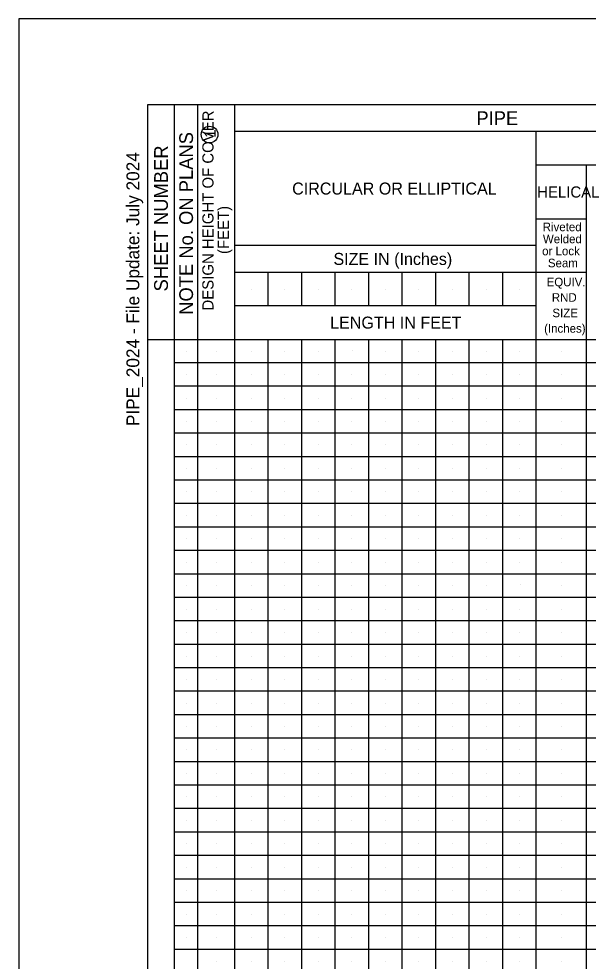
# Model space of a CAD drawing. Extents: x 0 to 1.42, y 0 to 0.92.
# Drawn here: x 0 to 0.2763, y 0.4596 to 0.9167 of the extents above; entities that cross this region are included whole.
import ezdxf

# ---------------------------------------------------------------- set-up
doc = ezdxf.new("R2010")
doc.units = 0
for name, color, linetype in [('#plot_shape', 7, 'Continuous'), ('P_ODOT_PLAN_Border', 7, 'Continuous'), ('P_ODOT_PLAN_General', 7, 'Continuous'), ('P_RDWY_PLAN_NotesTx', 7, 'Continuous')]:
    doc.layers.add(name, color=color, linetype=linetype)

msp = doc.modelspace()

# ---------------------------------------------------------------- linework, layer by layer
at = {"layer": '#plot_shape'}
msp.add_lwpolyline([(0, 0), (1.41667, 0), (1.41667, 0.91667), (0, 0.91667)], close=True, dxfattribs=at)
at = {"layer": 'P_ODOT_PLAN_Border'}
msp.add_lwpolyline([(0.0625, 0.04167), (1.39583, 0.04167), (1.39583, 0.875), (0.0625, 0.875)], close=True, dxfattribs=at)
at = {"layer": 'P_ODOT_PLAN_General'}
for p, q in [((0.07551, 0.26037), (0.07551, 0.875)), ((0.08689, 0.26037), (0.08689, 0.875)), ((0.10478, 0.26037), (0.10478, 0.875)), ((0.35681, 0.86199), (0.10478, 0.86199)), ((0.25112, 0.26037), (0.25112, 0.86199)), ((0.35681, 0.84573), (0.25112, 0.84573)), ((0.27551, 0.26037), (0.27551, 0.84573)), ((0.25112, 0.81972), (0.27551, 0.81972)), ((0.25112, 0.80671), (0.10478, 0.80671)), ((0.27551, 0.7937), (0.10478, 0.7937)), ((0.12104, 0.77744), (0.12104, 0.7937)), ((0.1373, 0.77744), (0.1373, 0.7937)), ((0.15356, 0.77744), (0.15356, 0.7937)), ((0.16982, 0.77744), (0.16982, 0.7937)), ((0.18608, 0.77744), (0.18608, 0.7937)), ((0.20234, 0.77744), (0.20234, 0.7937)), ((0.2186, 0.77744), (0.2186, 0.7937)), ((0.23486, 0.77744), (0.23486, 0.7937)), ((0.11291, 0.78557), (0.11291, 0.78557)), ((0.12917, 0.78557), (0.12917, 0.78557)), ((0.14543, 0.78557), (0.14543, 0.78557)), ((0.16169, 0.78557), (0.16169, 0.78557)), ((0.17795, 0.78557), (0.17795, 0.78557)), ((0.19421, 0.78557), (0.19421, 0.78557)), ((0.21047, 0.78557), (0.21047, 0.78557)), ((0.22673, 0.78557), (0.22673, 0.78557)), ((0.24299, 0.78557), (0.24299, 0.78557)), ((0.25112, 0.77744), (0.10478, 0.77744)), ((0.0625, 0.76118), (0.35681, 0.76118)), ((0.12104, 0.26037), (0.12104, 0.76118)), ((0.1373, 0.26037), (0.1373, 0.76118)), ((0.15356, 0.26037), (0.15356, 0.76118)), ((0.16982, 0.26037), (0.16982, 0.76118)), ((0.18608, 0.26037), (0.18608, 0.76118)), ((0.20234, 0.26037), (0.20234, 0.76118)), ((0.2186, 0.26037), (0.2186, 0.76118)), ((0.23486, 0.26037), (0.23486, 0.76118)), ((0.0812, 0.75549), (0.0812, 0.75549)), ((0.09583, 0.75549), (0.09583, 0.75549)), ((0.11291, 0.75549), (0.11291, 0.75549)), ((0.12917, 0.75549), (0.12917, 0.75549)), ((0.14543, 0.75549), (0.14543, 0.75549)), ((0.16176, 0.75562), (0.16176, 0.75562)), ((0.17795, 0.75549), (0.17795, 0.75549)), ((0.19421, 0.75549), (0.19421, 0.75549)), ((0.21047, 0.75549), (0.21047, 0.75549)), ((0.22673, 0.75549), (0.22673, 0.75549)), ((0.24299, 0.75549), (0.24299, 0.75549)), ((0.26331, 0.75549), (0.26331, 0.75549)), ((0.25112, 0.7498), (0.07551, 0.7498)), ((0.50965, 0.7498), (0.25112, 0.7498)), ((0.0812, 0.74411), (0.0812, 0.74411)), ((0.09583, 0.74411), (0.09583, 0.74411)), ((0.11291, 0.74411), (0.11291, 0.74411)), ((0.12917, 0.74411), (0.12917, 0.74411)), ((0.14543, 0.74411), (0.14543, 0.74411)), ((0.16169, 0.74411), (0.16169, 0.74411)), ((0.17795, 0.74411), (0.17795, 0.74411)), ((0.19421, 0.74411), (0.19421, 0.74411)), ((0.21047, 0.74411), (0.21047, 0.74411)), ((0.22673, 0.74411), (0.22673, 0.74411)), ((0.24299, 0.74411), (0.24299, 0.74411)), ((0.26331, 0.74411), (0.26331, 0.74411)), ((0.25112, 0.73842), (0.07551, 0.73842)), ((0.50965, 0.73842), (0.25112, 0.73842)), ((0.0812, 0.73273), (0.0812, 0.73273)), ((0.09583, 0.73273), (0.09583, 0.73273)), ((0.11291, 0.73273), (0.11291, 0.73273)), ((0.12917, 0.73273), (0.12917, 0.73273)), ((0.14543, 0.73273), (0.14543, 0.73273)), ((0.16169, 0.73273), (0.16169, 0.73273)), ((0.17795, 0.73273), (0.17795, 0.73273)), ((0.19421, 0.73273), (0.19421, 0.73273)), ((0.21047, 0.73273), (0.21047, 0.73273)), ((0.22673, 0.73273), (0.22673, 0.73273)), ((0.24299, 0.73273), (0.24299, 0.73273)), ((0.26331, 0.73273), (0.26331, 0.73273)), ((0.25112, 0.72703), (0.07551, 0.72703)), ((0.50965, 0.72703), (0.25112, 0.72703)), ((0.0812, 0.72134), (0.0812, 0.72134)), ((0.09583, 0.72134), (0.09583, 0.72134)), ((0.11291, 0.72134), (0.11291, 0.72134)), ((0.12917, 0.72134), (0.12917, 0.72134)), ((0.14543, 0.72134), (0.14543, 0.72134)), ((0.16169, 0.72134), (0.16169, 0.72134)), ((0.17795, 0.72134), (0.17795, 0.72134)), ((0.19421, 0.72134), (0.19421, 0.72134)), ((0.21047, 0.72134), (0.21047, 0.72134)), ((0.22673, 0.72134), (0.22673, 0.72134)), ((0.24299, 0.72134), (0.24299, 0.72134)), ((0.26331, 0.72134), (0.26331, 0.72134)), ((0.25112, 0.71565), (0.07551, 0.71565)), ((0.50965, 0.71565), (0.25112, 0.71565)), ((0.0812, 0.70996), (0.0812, 0.70996)), ((0.09583, 0.70996), (0.09583, 0.70996)), ((0.11291, 0.70996), (0.11291, 0.70996)), ((0.12917, 0.70996), (0.12917, 0.70996)), ((0.14543, 0.70996), (0.14543, 0.70996)), ((0.16169, 0.70996), (0.16169, 0.70996)), ((0.17795, 0.70996), (0.17795, 0.70996)), ((0.19421, 0.70996), (0.19421, 0.70996)), ((0.21047, 0.70996), (0.21047, 0.70996)), ((0.22673, 0.70996), (0.22673, 0.70996)), ((0.24299, 0.70996), (0.24299, 0.70996)), ((0.26331, 0.70996), (0.26331, 0.70996)), ((0.25112, 0.70427), (0.07551, 0.70427)), ((0.50965, 0.70427), (0.25112, 0.70427)), ((0.0812, 0.69858), (0.0812, 0.69858)), ((0.09583, 0.69858), (0.09583, 0.69858)), ((0.11291, 0.69858), (0.11291, 0.69858)), ((0.12917, 0.69858), (0.12917, 0.69858)), ((0.14543, 0.69858), (0.14543, 0.69858)), ((0.16169, 0.69858), (0.16169, 0.69858)), ((0.17795, 0.69858), (0.17795, 0.69858)), ((0.19421, 0.69858), (0.19421, 0.69858)), ((0.21047, 0.69858), (0.21047, 0.69858)), ((0.22673, 0.69858), (0.22673, 0.69858)), ((0.24299, 0.69858), (0.24299, 0.69858)), ((0.26331, 0.69858), (0.26331, 0.69858)), ((0.25112, 0.69289), (0.07551, 0.69289)), ((0.50965, 0.69289), (0.25112, 0.69289)), ((0.0812, 0.6872), (0.0812, 0.6872)), ((0.09583, 0.6872), (0.09583, 0.6872)), ((0.11291, 0.6872), (0.11291, 0.6872)), ((0.12917, 0.6872), (0.12917, 0.6872)), ((0.14543, 0.6872), (0.14543, 0.6872)), ((0.16169, 0.6872), (0.16169, 0.6872)), ((0.17795, 0.6872), (0.17795, 0.6872)), ((0.19421, 0.6872), (0.19421, 0.6872)), ((0.21047, 0.6872), (0.21047, 0.6872)), ((0.22673, 0.6872), (0.22673, 0.6872)), ((0.24299, 0.6872), (0.24299, 0.6872)), ((0.26331, 0.6872), (0.26331, 0.6872)), ((0.25112, 0.68151), (0.07551, 0.68151)), ((0.50965, 0.68151), (0.25112, 0.68151)), ((0.0812, 0.67582), (0.0812, 0.67582)), ((0.09583, 0.67582), (0.09583, 0.67582)), ((0.11291, 0.67582), (0.11291, 0.67582)), ((0.12917, 0.67582), (0.12917, 0.67582)), ((0.14543, 0.67582), (0.14543, 0.67582)), ((0.16169, 0.67582), (0.16169, 0.67582)), ((0.17795, 0.67582), (0.17795, 0.67582)), ((0.19421, 0.67582), (0.19421, 0.67582)), ((0.21047, 0.67582), (0.21047, 0.67582)), ((0.22673, 0.67582), (0.22673, 0.67582)), ((0.24299, 0.67582), (0.24299, 0.67582)), ((0.26331, 0.67582), (0.26331, 0.67582)), ((0.25112, 0.67012), (0.07551, 0.67012)), ((0.50965, 0.67012), (0.25112, 0.67012)), ((0.0812, 0.66443), (0.0812, 0.66443)), ((0.09583, 0.66443), (0.09583, 0.66443)), ((0.11291, 0.66443), (0.11291, 0.66443)), ((0.12917, 0.66443), (0.12917, 0.66443)), ((0.14543, 0.66443), (0.14543, 0.66443)), ((0.16169, 0.66443), (0.16169, 0.66443)), ((0.17795, 0.66443), (0.17795, 0.66443)), ((0.19421, 0.66443), (0.19421, 0.66443)), ((0.21047, 0.66443), (0.21047, 0.66443)), ((0.22673, 0.66443), (0.22673, 0.66443)), ((0.24299, 0.66443), (0.24299, 0.66443)), ((0.26331, 0.66443), (0.26331, 0.66443)), ((0.25112, 0.65874), (0.07551, 0.65874)), ((0.50965, 0.65874), (0.25112, 0.65874)), ((0.0812, 0.65305), (0.0812, 0.65305)), ((0.09583, 0.65305), (0.09583, 0.65305)), ((0.11291, 0.65305), (0.11291, 0.65305)), ((0.12917, 0.65305), (0.12917, 0.65305)), ((0.14543, 0.65305), (0.14543, 0.65305)), ((0.16169, 0.65305), (0.16169, 0.65305)), ((0.17795, 0.65305), (0.17795, 0.65305)), ((0.19421, 0.65305), (0.19421, 0.65305)), ((0.21047, 0.65305), (0.21047, 0.65305)), ((0.22695, 0.653), (0.22695, 0.653)), ((0.24299, 0.65305), (0.24299, 0.65305)), ((0.26331, 0.65305), (0.26331, 0.65305)), ((0.25112, 0.64736), (0.07551, 0.64736)), ((0.50965, 0.64736), (0.25112, 0.64736)), ((0.0812, 0.64167), (0.0812, 0.64167)), ((0.09583, 0.64167), (0.09583, 0.64167)), ((0.11291, 0.64167), (0.11291, 0.64167)), ((0.12917, 0.64167), (0.12917, 0.64167)), ((0.14543, 0.64167), (0.14543, 0.64167)), ((0.16169, 0.64167), (0.16169, 0.64167)), ((0.17795, 0.64167), (0.17795, 0.64167)), ((0.19421, 0.64167), (0.19421, 0.64167)), ((0.21047, 0.64167), (0.21047, 0.64167)), ((0.22673, 0.64167), (0.22673, 0.64167)), ((0.24364, 0.64213), (0.24364, 0.64213)), ((0.26331, 0.64167), (0.26331, 0.64167)), ((0.25112, 0.63598), (0.07551, 0.63598)), ((0.50965, 0.63598), (0.25112, 0.63598)), ((0.0812, 0.63029), (0.0812, 0.63029)), ((0.09583, 0.63029), (0.09583, 0.63029)), ((0.11291, 0.63029), (0.11291, 0.63029)), ((0.12917, 0.63029), (0.12917, 0.63029)), ((0.14543, 0.63029), (0.14543, 0.63029)), ((0.16169, 0.63029), (0.16169, 0.63029)), ((0.17795, 0.63029), (0.17795, 0.63029)), ((0.19421, 0.63029), (0.19421, 0.63029)), ((0.21047, 0.63029), (0.21047, 0.63029)), ((0.22673, 0.63029), (0.22673, 0.63029)), ((0.24299, 0.63029), (0.24299, 0.63029)), ((0.26331, 0.63029), (0.26331, 0.63029)), ((0.25112, 0.6246), (0.07551, 0.6246)), ((0.50965, 0.6246), (0.25112, 0.6246)), ((0.0812, 0.61891), (0.0812, 0.61891)), ((0.09583, 0.61891), (0.09583, 0.61891)), ((0.11291, 0.61891), (0.11291, 0.61891)), ((0.12917, 0.61891), (0.12917, 0.61891)), ((0.14543, 0.61891), (0.14543, 0.61891)), ((0.16169, 0.61891), (0.16169, 0.61891)), ((0.17795, 0.61891), (0.17795, 0.61891)), ((0.19421, 0.61891), (0.19421, 0.61891)), ((0.21047, 0.61891), (0.21047, 0.61891)), ((0.22673, 0.61891), (0.22673, 0.61891)), ((0.24299, 0.61891), (0.24299, 0.61891)), ((0.26331, 0.61891), (0.26331, 0.61891)), ((0.25112, 0.61321), (0.07551, 0.61321)), ((0.50965, 0.61321), (0.25112, 0.61321)), ((0.0812, 0.60752), (0.0812, 0.60752)), ((0.09583, 0.60752), (0.09583, 0.60752)), ((0.11291, 0.60752), (0.11291, 0.60752)), ((0.12917, 0.60752), (0.12917, 0.60752)), ((0.14543, 0.60752), (0.14543, 0.60752)), ((0.16169, 0.60752), (0.16169, 0.60752)), ((0.17795, 0.60752), (0.17795, 0.60752)), ((0.19421, 0.60752), (0.19421, 0.60752)), ((0.21047, 0.60752), (0.21047, 0.60752)), ((0.22673, 0.60752), (0.22673, 0.60752)), ((0.24299, 0.60752), (0.24299, 0.60752)), ((0.26331, 0.60752), (0.26331, 0.60752)), ((0.25112, 0.60183), (0.07551, 0.60183)), ((0.50965, 0.60183), (0.25112, 0.60183)), ((0.0812, 0.59614), (0.0812, 0.59614)), ((0.09583, 0.59614), (0.09583, 0.59614)), ((0.11291, 0.59614), (0.11291, 0.59614)), ((0.12917, 0.59614), (0.12917, 0.59614)), ((0.14543, 0.59614), (0.14543, 0.59614)), ((0.16169, 0.59614), (0.16169, 0.59614)), ((0.17795, 0.59614), (0.17795, 0.59614)), ((0.19421, 0.59614), (0.19421, 0.59614)), ((0.21047, 0.59614), (0.21047, 0.59614)), ((0.22673, 0.59614), (0.22673, 0.59614)), ((0.24299, 0.59614), (0.24299, 0.59614)), ((0.26331, 0.59614), (0.26331, 0.59614)), ((0.25112, 0.59045), (0.07551, 0.59045)), ((0.50965, 0.59045), (0.25112, 0.59045)), ((0.0812, 0.58476), (0.0812, 0.58476)), ((0.09583, 0.58476), (0.09583, 0.58476)), ((0.11291, 0.58476), (0.11291, 0.58476)), ((0.12917, 0.58476), (0.12917, 0.58476)), ((0.14543, 0.58476), (0.14543, 0.58476)), ((0.16169, 0.58476), (0.16169, 0.58476)), ((0.17795, 0.58476), (0.17795, 0.58476)), ((0.19421, 0.58476), (0.19421, 0.58476)), ((0.21047, 0.58476), (0.21047, 0.58476)), ((0.22673, 0.58476), (0.22673, 0.58476)), ((0.24299, 0.58476), (0.24299, 0.58476)), ((0.26331, 0.58476), (0.26331, 0.58476)), ((0.25112, 0.57907), (0.07551, 0.57907)), ((0.50965, 0.57907), (0.25112, 0.57907)), ((0.0812, 0.57338), (0.0812, 0.57338)), ((0.09583, 0.57338), (0.09583, 0.57338)), ((0.11291, 0.57338), (0.11291, 0.57338)), ((0.12917, 0.57338), (0.12917, 0.57338)), ((0.14543, 0.57338), (0.14543, 0.57338)), ((0.16169, 0.57338), (0.16169, 0.57338)), ((0.17795, 0.57338), (0.17795, 0.57338)), ((0.19421, 0.57338), (0.19421, 0.57338)), ((0.21047, 0.57338), (0.21047, 0.57338)), ((0.22673, 0.57338), (0.22673, 0.57338)), ((0.24299, 0.57338), (0.24299, 0.57338)), ((0.26331, 0.57338), (0.26331, 0.57338)), ((0.25112, 0.56769), (0.07551, 0.56769)), ((0.50965, 0.56769), (0.25112, 0.56769)), ((0.0812, 0.562), (0.0812, 0.562)), ((0.09583, 0.562), (0.09583, 0.562)), ((0.11291, 0.562), (0.11291, 0.562)), ((0.12917, 0.562), (0.12917, 0.562)), ((0.14543, 0.562), (0.14543, 0.562)), ((0.16169, 0.562), (0.16169, 0.562)), ((0.17795, 0.562), (0.17795, 0.562)), ((0.19421, 0.562), (0.19421, 0.562)), ((0.21047, 0.562), (0.21047, 0.562)), ((0.22673, 0.562), (0.22673, 0.562)), ((0.24299, 0.562), (0.24299, 0.562)), ((0.26331, 0.562), (0.26331, 0.562)), ((0.25112, 0.5563), (0.07551, 0.5563)), ((0.50965, 0.5563), (0.25112, 0.5563)), ((0.0812, 0.55061), (0.0812, 0.55061)), ((0.09583, 0.55061), (0.09583, 0.55061)), ((0.11291, 0.55061), (0.11291, 0.55061)), ((0.12917, 0.55061), (0.12917, 0.55061)), ((0.14543, 0.55061), (0.14543, 0.55061)), ((0.16169, 0.55061), (0.16169, 0.55061)), ((0.17795, 0.55061), (0.17795, 0.55061)), ((0.19421, 0.55061), (0.19421, 0.55061)), ((0.21047, 0.55061), (0.21047, 0.55061)), ((0.22673, 0.55061), (0.22673, 0.55061)), ((0.24299, 0.55061), (0.24299, 0.55061)), ((0.26331, 0.55061), (0.26331, 0.55061)), ((0.25112, 0.54492), (0.07551, 0.54492)), ((0.08689, 0.53354), (0.08689, 0.54492)), ((0.50965, 0.54492), (0.25112, 0.54492)), ((0.0812, 0.53923), (0.0812, 0.53923)), ((0.09583, 0.53923), (0.09583, 0.53923)), ((0.11291, 0.53923), (0.11291, 0.53923)), ((0.12917, 0.53923), (0.12917, 0.53923)), ((0.14543, 0.53923), (0.14543, 0.53923)), ((0.16169, 0.53923), (0.16169, 0.53923)), ((0.17795, 0.53923), (0.17795, 0.53923)), ((0.19421, 0.53923), (0.19421, 0.53923)), ((0.21047, 0.53923), (0.21047, 0.53923)), ((0.22673, 0.53923), (0.22673, 0.53923)), ((0.24299, 0.53923), (0.24299, 0.53923)), ((0.26331, 0.53923), (0.26331, 0.53923)), ((0.25112, 0.53354), (0.07551, 0.53354)), ((0.50965, 0.53354), (0.25112, 0.53354)), ((0.0812, 0.52785), (0.0812, 0.52785)), ((0.09583, 0.52785), (0.09583, 0.52785)), ((0.11291, 0.52785), (0.11291, 0.52785)), ((0.12917, 0.52785), (0.12917, 0.52785)), ((0.14543, 0.52785), (0.14543, 0.52785)), ((0.16169, 0.52785), (0.16169, 0.52785)), ((0.17795, 0.52785), (0.17795, 0.52785)), ((0.19421, 0.52785), (0.19421, 0.52785)), ((0.21047, 0.52785), (0.21047, 0.52785)), ((0.22673, 0.52785), (0.22673, 0.52785)), ((0.24299, 0.52785), (0.24299, 0.52785)), ((0.26331, 0.52785), (0.26331, 0.52785)), ((0.25112, 0.52216), (0.07551, 0.52216)), ((0.50965, 0.52216), (0.25112, 0.52216)), ((0.0812, 0.51647), (0.0812, 0.51647)), ((0.09583, 0.51647), (0.09583, 0.51647)), ((0.11291, 0.51647), (0.11291, 0.51647)), ((0.12917, 0.51647), (0.12917, 0.51647)), ((0.14543, 0.51647), (0.14543, 0.51647)), ((0.16169, 0.51647), (0.16169, 0.51647)), ((0.17795, 0.51647), (0.17795, 0.51647)), ((0.19421, 0.51647), (0.19421, 0.51647)), ((0.21047, 0.51647), (0.21047, 0.51647)), ((0.22673, 0.51647), (0.22673, 0.51647)), ((0.24299, 0.51647), (0.24299, 0.51647)), ((0.26331, 0.51647), (0.26331, 0.51647)), ((0.25112, 0.51078), (0.07551, 0.51078)), ((0.50965, 0.51078), (0.25112, 0.51078)), ((0.0812, 0.50508), (0.0812, 0.50508)), ((0.09583, 0.50508), (0.09583, 0.50508)), ((0.11291, 0.50508), (0.11291, 0.50508)), ((0.12917, 0.50508), (0.12917, 0.50508)), ((0.14543, 0.50508), (0.14543, 0.50508)), ((0.16169, 0.50508), (0.16169, 0.50508)), ((0.17795, 0.50508), (0.17795, 0.50508)), ((0.19421, 0.50508), (0.19421, 0.50508)), ((0.21047, 0.50508), (0.21047, 0.50508)), ((0.22673, 0.50508), (0.22673, 0.50508)), ((0.24299, 0.50508), (0.24299, 0.50508)), ((0.26331, 0.50508), (0.26331, 0.50508)), ((0.25112, 0.49939), (0.07551, 0.49939)), ((0.50965, 0.49939), (0.25112, 0.49939)), ((0.0812, 0.4937), (0.0812, 0.4937)), ((0.09583, 0.4937), (0.09583, 0.4937)), ((0.11291, 0.4937), (0.11291, 0.4937)), ((0.12917, 0.4937), (0.12917, 0.4937)), ((0.14543, 0.4937), (0.14543, 0.4937)), ((0.16169, 0.4937), (0.16169, 0.4937)), ((0.17795, 0.4937), (0.17795, 0.4937)), ((0.19421, 0.4937), (0.19421, 0.4937)), ((0.21047, 0.4937), (0.21047, 0.4937)), ((0.22673, 0.4937), (0.22673, 0.4937)), ((0.24299, 0.4937), (0.24299, 0.4937)), ((0.26331, 0.4937), (0.26331, 0.4937)), ((0.25112, 0.48801), (0.07551, 0.48801)), ((0.50965, 0.48801), (0.25112, 0.48801)), ((0.0812, 0.48232), (0.0812, 0.48232)), ((0.09583, 0.48232), (0.09583, 0.48232)), ((0.11291, 0.48232), (0.11291, 0.48232)), ((0.12917, 0.48232), (0.12917, 0.48232)), ((0.14543, 0.48232), (0.14543, 0.48232)), ((0.16169, 0.48232), (0.16169, 0.48232)), ((0.17795, 0.48232), (0.17795, 0.48232)), ((0.19421, 0.48232), (0.19421, 0.48232)), ((0.21047, 0.48232), (0.21047, 0.48232)), ((0.22673, 0.48232), (0.22673, 0.48232)), ((0.24299, 0.48232), (0.24299, 0.48232)), ((0.26331, 0.48232), (0.26331, 0.48232)), ((0.25112, 0.47663), (0.07551, 0.47663)), ((0.50965, 0.47663), (0.25112, 0.47663)), ((0.0812, 0.47094), (0.0812, 0.47094)), ((0.09583, 0.47094), (0.09583, 0.47094)), ((0.11291, 0.47094), (0.11291, 0.47094)), ((0.12917, 0.47094), (0.12917, 0.47094)), ((0.14543, 0.47094), (0.14543, 0.47094)), ((0.16169, 0.47094), (0.16169, 0.47094)), ((0.17795, 0.47094), (0.17795, 0.47094)), ((0.19421, 0.47094), (0.19421, 0.47094)), ((0.21047, 0.47094), (0.21047, 0.47094)), ((0.22673, 0.47094), (0.22673, 0.47094)), ((0.24299, 0.47094), (0.24299, 0.47094)), ((0.26331, 0.47094), (0.26331, 0.47094)), ((0.25112, 0.46525), (0.07551, 0.46525)), ((0.50965, 0.46525), (0.25112, 0.46525)), ((0.09583, 0.45956), (0.09583, 0.45956)), ((0.11291, 0.45956), (0.11291, 0.45956)), ((0.12917, 0.45956), (0.12917, 0.45956)), ((0.14543, 0.45956), (0.14543, 0.45956)), ((0.16169, 0.45956), (0.16169, 0.45956)), ((0.17795, 0.45956), (0.17795, 0.45956)), ((0.19421, 0.45956), (0.19421, 0.45956)), ((0.21047, 0.45956), (0.21047, 0.45956)), ((0.22673, 0.45956), (0.22673, 0.45956)), ((0.24299, 0.45956), (0.24299, 0.45956)), ((0.26331, 0.45956), (0.26331, 0.45956))]:
    msp.add_line(p, q, dxfattribs=at)
at = {"layer": 'P_RDWY_PLAN_NotesTx'}
msp.add_circle((0.09258, 0.86053), 0.00407, dxfattribs=at)

# ---------------------------------------------------------------- texts
for s, height, p in [('DESIGN HEIGHT OF COVER', 0.0054167, (0.09448, 0.77518)), ('NOTE No. ON PLANS', 0.0066667, (0.08453, 0.77309)), ('1', 0.00542, (0.09549, 0.859)), ('SHEET NUMBER', 0.0066667, (0.07234, 0.78443)), ('PIPE_2024 - File Update: July 2024', 0.00625, (0.05848, 0.71912)), ('(FEET)', 0.005417, (0.10199, 0.80258))]:
    msp.add_text(s, height=height, rotation=90, dxfattribs=at).set_placement(p)
for s, height, p in [('PIPE', 0.006667, (0.22205, 0.86516)), ('CIRCULAR OR ELLIPTICAL', 0.0058333, (0.13265, 0.83143)), ('HELICAL', 0.005417, (0.25158, 0.82997)), ('Riveted', 0.004167, (0.25425, 0.81364)), ('Welded', 0.004167, (0.25435, 0.80781)), ('or Lock', 0.004167, (0.25398, 0.80197)), ('SIZE IN (Inches)', 0.0058333, (0.15269, 0.79729)), ('Seam', 0.004167, (0.25677, 0.79614)), ('EQUIV.', 0.004167, (0.25614, 0.78692)), ('RND', 0.004167, (0.25868, 0.77942)), ('SIZE', 0.004167, (0.25896, 0.77192)), ('LENGTH IN FEET', 0.0058333, (0.1511, 0.76639)), ('(Inches)', 0.004167, (0.25493, 0.76442))]:
    msp.add_text(s, height=height, dxfattribs=at).set_placement(p)

doc.saveas('drawing.dxf')
